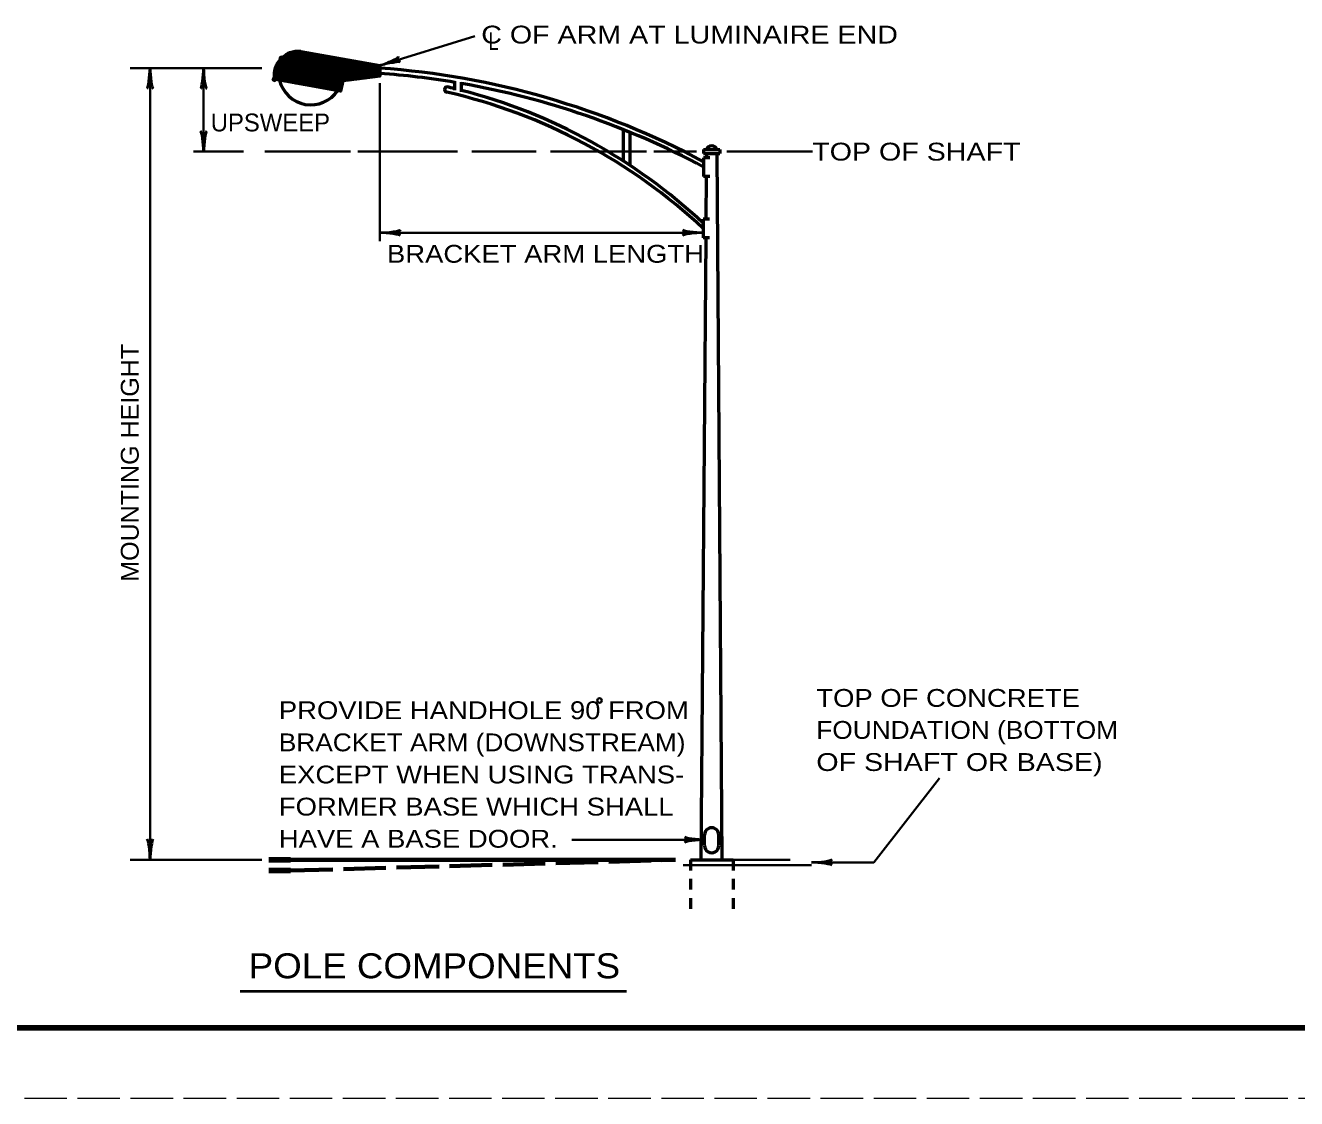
# Model space of a CAD drawing. Extents: x 6488 to 7168, y 276 to 716.
# Drawn here: x 6801.8 to 6981.4, y 276 to 427.7 of the extents above; entities that cross this region are included whole.
import ezdxf

# ---------------------------------------------------------------- set-up
doc = ezdxf.new("R2010")
doc.units = 0
doc.header["$PDMODE"] = 32
doc.header["$PDSIZE"] = 0.5
doc.linetypes.add('LONG_DASHED', pattern=[7.5, 6, -1.5])
doc.linetypes.add('SHORT_DASHED', pattern=[2.7, 1.5, -1.2])
doc.layers.add('1', color=7, linetype='Continuous', lineweight=35)
doc.layers.add('61', color=7, linetype='Continuous', lineweight=35)

msp = doc.modelspace()

# ---------------------------------------------------------------- linework, layer by layer
at = {"layer": '1'}
for p, q in [((6851.87, 421.998), (6865.29, 426.138)), ((6835.19, 421.618), (6816.59, 421.618)), ((6819.39, 421.618), (6819.39, 309.738)), ((6826.95, 409.818), (6826.95, 421.618)), ((6851.87, 419.478), (6851.87, 397.158)), ((6832.59, 409.818), (6825.55, 409.818)), ((6847.71, 409.818), (6835.63, 409.818)), ((6862.83, 409.818), (6848.73, 409.818)), ((6873.93, 409.818), (6864.85, 409.818)), ((6889.55, 409.818), (6875.95, 409.818)), ((6890.55, 409.818), (6896.61, 409.818)), ((6912.99, 409.818), (6900.89, 409.818)), ((6897.55, 398.358), (6851.87, 398.358)), ((6930.91, 321.278), (6921.65, 309.378)), ((6897.81, 312.578), (6878.97, 312.578)), ((6835.19, 309.738), (6816.59, 309.738)), ((6894.71, 308.978), (6912.85, 308.978)), ((6901.77, 309.738), (6909.83, 309.738)), ((6912.85, 309.378), (6921.65, 309.378))]:
    msp.add_line(p, q, dxfattribs=at)
at = {"layer": '1', "lineweight": 53}
for p, q in [((6836.99, 421.318), (6839.59, 423.898)), ((6837.03, 421.438), (6839.45, 423.858)), ((6837.51, 421.718), (6839.73, 423.918)), ((6837.63, 421.718), (6839.85, 423.958)), ((6837.73, 421.718), (6839.97, 423.958)), ((6837.83, 421.718), (6840.09, 423.978)), ((6837.95, 421.718), (6840.21, 423.978)), ((6838.05, 421.718), (6840.31, 423.978)), ((6838.15, 421.718), (6840.43, 423.978)), ((6838.27, 421.718), (6840.53, 423.978)), ((6838.37, 421.718), (6840.63, 423.978)), ((6838.47, 421.718), (6840.73, 423.978)), ((6838.59, 421.718), (6840.81, 423.958)), ((6838.69, 421.718), (6840.91, 423.938)), ((6838.79, 421.718), (6840.99, 423.918)), ((6838.91, 421.718), (6841.09, 423.898)), ((6839.01, 421.718), (6841.19, 423.898)), ((6839.11, 421.718), (6841.27, 423.878)), ((6839.23, 421.718), (6841.37, 423.858)), ((6837.09, 421.598), (6839.29, 423.818)), ((6837.13, 421.758), (6839.13, 423.758)), ((6837.21, 421.958), (6838.95, 423.678)), ((6837.31, 422.158), (6838.73, 423.578)), ((6837.47, 422.418), (6838.47, 423.418)), ((6839.33, 421.718), (6841.45, 423.838)), ((6839.43, 421.718), (6841.55, 423.818)), ((6839.55, 421.718), (6841.63, 423.818)), ((6839.65, 421.718), (6841.73, 423.798)), ((6839.77, 421.718), (6841.81, 423.778)), ((6839.87, 421.718), (6841.91, 423.758)), ((6839.97, 421.718), (6841.99, 423.738)), ((6840.09, 421.718), (6842.09, 423.738)), ((6840.19, 421.718), (6842.19, 423.718)), ((6840.29, 421.718), (6842.27, 423.698)), ((6840.41, 421.718), (6842.37, 423.678)), ((6840.51, 421.718), (6842.45, 423.658)), ((6840.61, 421.718), (6842.55, 423.658)), ((6840.73, 421.718), (6842.63, 423.638)), ((6840.83, 421.718), (6842.73, 423.618)), ((6840.93, 421.718), (6842.81, 423.598)), ((6841.05, 421.718), (6842.91, 423.578)), ((6841.15, 421.718), (6842.99, 423.558)), ((6841.25, 421.718), (6843.09, 423.558)), ((6841.37, 421.718), (6843.19, 423.538)), ((6841.47, 421.718), (6843.27, 423.518)), ((6841.57, 421.718), (6843.37, 423.498)), ((6841.69, 421.718), (6843.45, 423.478)), ((6841.79, 421.718), (6843.55, 423.478)), ((6841.89, 421.718), (6843.63, 423.458)), ((6842.01, 421.718), (6843.73, 423.438)), ((6842.11, 421.718), (6843.81, 423.418)), ((6842.21, 421.718), (6843.91, 423.398)), ((6842.33, 421.718), (6843.99, 423.398)), ((6842.43, 421.718), (6844.09, 423.378)), ((6842.55, 421.718), (6844.19, 423.358)), ((6842.65, 421.718), (6844.27, 423.338)), ((6842.75, 421.718), (6844.37, 423.318)), ((6842.87, 421.718), (6844.45, 423.318)), ((6842.97, 421.718), (6844.55, 423.298)), ((6843.07, 421.718), (6844.63, 423.278)), ((6843.19, 421.718), (6844.73, 423.258)), ((6843.29, 421.718), (6844.81, 423.238)), ((6843.39, 421.718), (6844.91, 423.238)), ((6843.51, 421.718), (6844.99, 423.218)), ((6843.61, 421.718), (6845.09, 423.198)), ((6843.71, 421.718), (6845.19, 423.178)), ((6843.83, 421.718), (6845.27, 423.158)), ((6843.93, 421.718), (6845.37, 423.158)), ((6844.03, 421.718), (6845.45, 423.138)), ((6844.15, 421.718), (6845.55, 423.118)), ((6844.25, 421.718), (6845.63, 423.098)), ((6844.35, 421.718), (6845.73, 423.078)), ((6844.47, 421.718), (6845.81, 423.078)), ((6844.57, 421.718), (6845.91, 423.058)), ((6844.67, 421.718), (6845.99, 423.038)), ((6844.79, 421.718), (6846.09, 423.018)), ((6844.89, 421.718), (6846.19, 422.998)), ((6844.99, 421.718), (6846.27, 422.998)), ((6845.11, 421.718), (6846.37, 422.978)), ((6845.21, 421.718), (6846.45, 422.958)), ((6845.31, 421.718), (6846.55, 422.938)), ((6845.43, 421.718), (6846.63, 422.918)), ((6845.53, 421.718), (6846.73, 422.918)), ((6845.65, 421.718), (6846.81, 422.898)), ((6845.75, 421.718), (6846.91, 422.878)), ((6845.85, 421.718), (6846.99, 422.858)), ((6845.97, 421.718), (6847.09, 422.838)), ((6846.07, 421.718), (6847.17, 422.838)), ((6846.17, 421.718), (6847.27, 422.818)), ((6846.29, 421.718), (6847.37, 422.798)), ((6846.39, 421.718), (6847.45, 422.778)), ((6846.49, 421.718), (6847.55, 422.758)), ((6846.61, 421.718), (6847.63, 422.758)), ((6846.71, 421.718), (6847.73, 422.738)), ((6846.81, 421.718), (6847.81, 422.718)), ((6846.93, 421.718), (6847.91, 422.698)), ((6847.03, 421.718), (6847.99, 422.678)), ((6847.13, 421.718), (6848.09, 422.678)), ((6847.25, 421.718), (6848.17, 422.658)), ((6847.35, 421.718), (6848.27, 422.638)), ((6847.45, 421.718), (6848.37, 422.618)), ((6847.57, 421.718), (6848.45, 422.598)), ((6847.67, 421.718), (6848.55, 422.598)), ((6847.77, 421.718), (6848.63, 422.578)), ((6847.89, 421.718), (6848.73, 422.558)), ((6847.99, 421.718), (6848.81, 422.538)), ((6848.09, 421.718), (6848.91, 422.518)), ((6848.21, 421.718), (6848.99, 422.518)), ((6848.31, 421.718), (6849.09, 422.498)), ((6848.43, 421.718), (6849.17, 422.478)), ((6848.53, 421.718), (6849.27, 422.458)), ((6848.63, 421.718), (6849.37, 422.438)), ((6848.75, 421.718), (6849.45, 422.438)), ((6848.85, 421.718), (6849.55, 422.418)), ((6848.95, 421.718), (6849.63, 422.398)), ((6849.07, 421.718), (6849.73, 422.378)), ((6849.17, 421.718), (6849.81, 422.358)), ((6849.27, 421.718), (6849.91, 422.358)), ((6849.39, 421.718), (6849.99, 422.338)), ((6849.49, 421.718), (6850.09, 422.318)), ((6849.59, 421.718), (6850.17, 422.298)), ((6849.71, 421.718), (6850.27, 422.278)), ((6849.81, 421.718), (6850.37, 422.278)), ((6849.91, 421.718), (6850.45, 422.258)), ((6850.03, 421.718), (6850.55, 422.238)), ((6850.13, 421.718), (6850.63, 422.218)), ((6850.23, 421.718), (6850.73, 422.198)), ((6850.35, 421.718), (6850.81, 422.198)), ((6850.45, 421.718), (6850.91, 422.178)), ((6850.55, 421.718), (6850.99, 422.158)), ((6850.67, 421.718), (6851.09, 422.138)), ((6850.77, 421.718), (6851.17, 422.118)), ((6850.87, 421.718), (6851.27, 422.118)), ((6850.99, 421.718), (6851.37, 422.098)), ((6851.09, 421.718), (6851.45, 422.078)), ((6851.21, 421.718), (6851.55, 422.058)), ((6836.91, 420.798), (6837.65, 421.538)), ((6836.91, 420.678), (6837.75, 421.538)), ((6836.91, 420.578), (6837.87, 421.538)), ((6836.91, 420.478), (6837.97, 421.538)), ((6836.91, 420.358), (6838.07, 421.538)), ((6836.91, 420.278), (6838.19, 421.538)), ((6836.93, 420.918), (6837.53, 421.538)), ((6836.93, 420.178), (6838.29, 421.538)), ((6836.93, 420.078), (6838.39, 421.538)), ((6836.95, 421.038), (6837.49, 421.598)), ((6836.97, 421.178), (6837.49, 421.698)), ((6836.99, 420.018), (6838.51, 421.538)), ((6837.09, 419.998), (6838.61, 421.538)), ((6837.17, 419.998), (6838.71, 421.538)), ((6837.27, 419.978), (6838.83, 421.538)), ((6837.35, 419.958), (6838.93, 421.538)), ((6837.45, 419.938), (6839.03, 421.538)), ((6837.53, 419.918), (6839.15, 421.538)), ((6837.63, 419.918), (6839.25, 421.538)), ((6837.73, 419.898), (6839.35, 421.538)), ((6837.81, 419.878), (6839.47, 421.538)), ((6837.91, 419.858), (6839.57, 421.538)), ((6837.99, 419.838), (6839.67, 421.538)), ((6838.09, 419.838), (6839.79, 421.538)), ((6838.17, 419.818), (6839.89, 421.538)), ((6838.27, 419.798), (6839.99, 421.538)), ((6838.35, 419.778), (6840.11, 421.538)), ((6838.45, 419.758), (6840.21, 421.538)), ((6838.53, 419.758), (6840.31, 421.538)), ((6838.63, 419.738), (6840.43, 421.538)), ((6838.71, 419.718), (6840.53, 421.538)), ((6838.81, 419.698), (6840.65, 421.538)), ((6838.91, 419.678), (6840.75, 421.538)), ((6838.99, 419.678), (6840.85, 421.538)), ((6839.09, 419.658), (6840.97, 421.538)), ((6839.17, 419.638), (6841.07, 421.538)), ((6839.27, 419.618), (6841.17, 421.538)), ((6839.35, 419.598), (6841.29, 421.538)), ((6839.45, 419.598), (6841.39, 421.538)), ((6839.53, 419.578), (6841.49, 421.538)), ((6839.63, 419.558), (6841.61, 421.538)), ((6839.71, 419.538), (6841.71, 421.538)), ((6839.81, 419.518), (6841.81, 421.538)), ((6839.91, 419.518), (6841.93, 421.538)), ((6839.99, 419.498), (6842.03, 421.538)), ((6840.09, 419.478), (6842.13, 421.538)), ((6840.17, 419.458), (6842.25, 421.538)), ((6840.27, 419.438), (6842.35, 421.538)), ((6840.35, 419.438), (6842.45, 421.538)), ((6840.45, 419.418), (6842.57, 421.538)), ((6840.53, 419.398), (6842.67, 421.538)), ((6840.63, 419.378), (6842.77, 421.538)), ((6840.71, 419.358), (6842.89, 421.538)), ((6840.81, 419.338), (6842.99, 421.538)), ((6840.91, 419.338), (6843.09, 421.538)), ((6840.99, 419.318), (6843.21, 421.538)), ((6841.09, 419.298), (6843.31, 421.538)), ((6841.17, 419.278), (6843.43, 421.538)), ((6841.27, 419.258), (6843.53, 421.538)), ((6841.35, 419.258), (6843.63, 421.538)), ((6841.45, 419.238), (6843.75, 421.538)), ((6841.53, 419.218), (6843.85, 421.538)), ((6841.63, 419.198), (6843.95, 421.538)), ((6841.71, 419.178), (6844.07, 421.538)), ((6841.81, 419.178), (6844.17, 421.538)), ((6841.91, 419.158), (6844.27, 421.538)), ((6841.99, 419.138), (6844.39, 421.538)), ((6842.09, 419.118), (6844.49, 421.538)), ((6842.17, 419.098), (6844.59, 421.538)), ((6842.27, 419.098), (6844.71, 421.538)), ((6842.35, 419.078), (6844.81, 421.538)), ((6842.45, 419.058), (6844.91, 421.538)), ((6842.53, 419.038), (6845.03, 421.538)), ((6842.63, 419.018), (6845.13, 421.538)), ((6842.71, 419.018), (6845.23, 421.538)), ((6842.81, 418.998), (6845.35, 421.538)), ((6842.91, 418.978), (6845.45, 421.538)), ((6842.99, 418.958), (6845.55, 421.538)), ((6843.09, 418.938), (6845.67, 421.538)), ((6843.17, 418.938), (6845.77, 421.538)), ((6843.27, 418.918), (6845.87, 421.538)), ((6843.35, 418.898), (6845.99, 421.538)), ((6843.45, 418.878), (6846.09, 421.538)), ((6843.53, 418.858), (6846.21, 421.538)), ((6843.63, 418.858), (6846.31, 421.538)), ((6843.71, 418.838), (6846.41, 421.538)), ((6843.81, 418.818), (6846.53, 421.538)), ((6843.91, 418.798), (6846.63, 421.538)), ((6843.99, 418.778), (6846.73, 421.538)), ((6844.09, 418.778), (6846.85, 421.538)), ((6844.17, 418.758), (6846.95, 421.538)), ((6844.27, 418.738), (6847.05, 421.538)), ((6844.35, 418.718), (6847.17, 421.538)), ((6844.45, 418.698), (6847.27, 421.538)), ((6844.53, 418.698), (6847.37, 421.538)), ((6844.63, 418.678), (6847.49, 421.538)), ((6844.71, 418.658), (6847.59, 421.538)), ((6844.81, 418.638), (6847.69, 421.538)), ((6844.91, 418.618), (6847.81, 421.538)), ((6844.99, 418.618), (6847.91, 421.538)), ((6845.09, 418.598), (6848.01, 421.538)), ((6845.17, 418.578), (6848.13, 421.538)), ((6845.27, 418.558), (6848.23, 421.538)), ((6846.65, 419.858), (6848.33, 421.538)), ((6846.79, 419.858), (6848.45, 421.538)), ((6846.91, 419.878), (6848.55, 421.538)), ((6847.03, 419.898), (6848.65, 421.538)), ((6847.15, 419.918), (6848.77, 421.538)), ((6847.27, 419.918), (6848.87, 421.538)), ((6847.39, 419.938), (6848.97, 421.538)), ((6847.51, 419.958), (6849.09, 421.538)), ((6847.63, 419.978), (6849.19, 421.538)), ((6847.75, 419.978), (6849.31, 421.538)), ((6847.87, 419.998), (6849.41, 421.538)), ((6847.99, 420.018), (6849.51, 421.538)), ((6848.13, 420.038), (6849.63, 421.538)), ((6848.25, 420.038), (6849.73, 421.538)), ((6848.37, 420.058), (6849.83, 421.538)), ((6848.49, 420.078), (6849.95, 421.538)), ((6848.61, 420.098), (6850.05, 421.538)), ((6848.73, 420.098), (6850.15, 421.538)), ((6848.85, 420.118), (6850.27, 421.538)), ((6848.97, 420.138), (6850.37, 421.538)), ((6849.09, 420.158), (6850.47, 421.538)), ((6849.21, 420.158), (6850.59, 421.538)), ((6849.33, 420.178), (6850.69, 421.538)), ((6849.47, 420.198), (6850.79, 421.538)), ((6849.59, 420.218), (6850.91, 421.538)), ((6849.71, 420.218), (6851.01, 421.538)), ((6849.83, 420.238), (6851.11, 421.538)), ((6849.95, 420.258), (6851.23, 421.538)), ((6850.07, 420.278), (6851.33, 421.538)), ((6850.19, 420.278), (6851.43, 421.538)), ((6850.31, 420.298), (6851.87, 421.858)), ((6850.43, 420.318), (6851.87, 421.758)), ((6850.55, 420.338), (6851.87, 421.638)), ((6850.69, 420.338), (6851.87, 421.538)), ((6850.81, 420.358), (6851.87, 421.438)), ((6850.93, 420.378), (6851.87, 421.318)), ((6851.05, 420.398), (6851.87, 421.218)), ((6851.17, 420.398), (6851.87, 421.118)), ((6851.29, 420.418), (6851.87, 420.998)), ((6851.31, 421.718), (6851.63, 422.038)), ((6851.41, 421.718), (6851.73, 422.038)), ((6851.41, 420.438), (6851.87, 420.898)), ((6851.49, 421.698), (6851.81, 422.018)), ((6851.49, 421.598), (6851.87, 421.958)), ((6851.53, 420.458), (6851.87, 420.798)), ((6851.65, 420.458), (6851.87, 420.678)), ((6851.77, 420.478), (6851.87, 420.578)), ((6845.35, 418.538), (6846.61, 419.798)), ((6845.45, 418.538), (6846.59, 419.658)), ((6845.53, 418.518), (6846.55, 419.518)), ((6845.63, 418.498), (6846.51, 419.398)), ((6845.71, 418.478), (6846.49, 419.258)), ((6845.81, 418.458), (6846.45, 419.118)), ((6845.89, 418.458), (6846.43, 418.978)), ((6845.99, 418.438), (6846.39, 418.838)), ((6846.09, 418.418), (6846.35, 418.698)), ((6846.17, 418.398), (6846.33, 418.558)), ((6862.45, 418.518), (6862.45, 419.798)), ((6863.41, 418.278), (6863.41, 419.638)), ((6846.27, 418.378), (6846.29, 418.418)), ((6886.27, 408.478), (6886.27, 412.938)), ((6887.21, 407.878), (6887.21, 412.538)), ((6897.61, 410.098), (6899.89, 410.098)), ((6897.61, 410.098), (6897.61, 409.538)), ((6897.61, 409.538), (6899.89, 409.538)), ((6897.99, 409.538), (6897.99, 408.958)), ((6900.25, 309.738), (6899.51, 409.538)), ((6899.89, 410.098), (6899.89, 409.538)), ((6898.49, 408.958), (6897.61, 408.958)), ((6897.61, 408.958), (6897.61, 406.318)), ((6898.49, 406.318), (6897.61, 406.318)), ((6897.97, 406.318), (6897.93, 400.258)), ((6898.43, 400.258), (6897.55, 400.258)), ((6897.55, 400.258), (6897.55, 397.618)), ((6897.91, 397.618), (6897.23, 309.738)), ((6898.43, 397.618), (6897.55, 397.618)), ((6897.75, 311.758), (6897.75, 313.258)), ((6899.75, 311.758), (6899.75, 313.258)), ((6895.73, 309.738), (6901.77, 309.738))]:
    msp.add_line(p, q, dxfattribs=at)
at = {"layer": '1', "lineweight": 106}
for p, q in [((6836.19, 309.738), (6839.23, 309.738)), ((6836.19, 308.218), (6839.23, 308.218))]:
    msp.add_line(p, q, dxfattribs=at)
at = {"layer": '1', "lineweight": 70}
msp.add_line((6839.23, 309.738), (6893.65, 309.738), dxfattribs=at)
at = {"layer": '1', "linetype": 'LONG_DASHED', "lineweight": 70}
msp.add_line((6839.23, 308.218), (6893.65, 309.738), dxfattribs=at)
at = {"layer": '1', "linetype": 'SHORT_DASHED', "lineweight": 53}
for p, q in [((6895.73, 309.738), (6895.73, 301.678)), ((6901.77, 309.738), (6901.77, 301.678))]:
    msp.add_line(p, q, dxfattribs=at)
at = {"layer": '1', "lineweight": 40}
msp.add_line((6832.11, 291.178), (6886.69, 291.178), dxfattribs=at)
at = {"layer": '1', "lineweight": 53}
msp.add_lwpolyline([(6840.71, 423.978), (6851.87, 421.998), (6851.87, 420.498), (6846.63, 419.838), (6846.29, 418.378), (6836.95, 420.038)], dxfattribs=at)
msp.add_lwpolyline([(6837.49, 421.718), (6851.49, 421.718), (6851.49, 421.538), (6837.49, 421.538)], close=True, dxfattribs=at)
at = {"layer": '1'}
msp.add_circle((6882.902, 332.255), 0.325, dxfattribs=at)
at = {"layer": '1', "lineweight": 53}
for centre, radius, start, end in [((6840.361, 420.534), 3.456, 84.23953, 188.38162), ((6843.679, 307.63), 114.289, 61.84402, 85.88743), ((6843.679, 306.874), 114.289, 80.54208, 85.88743), ((6842.122, 421.001), 4.57, 193.94762, 326.05059), ((6861.388, 418.601), 0.383, 99.37484, 260.62516), ((6843.798, 342.391), 78.568, 76.2603, 77.11012), ((6843.679, 306.874), 114.289, 61.84402, 80.06146), ((6843.798, 342.391), 78.568, 46.83897, 75.54976), ((6861.5, 418.85), 0.651, 235.53017, 254.38288), ((6843.798, 341.635), 78.568, 46.83897, 77.11012), ((6898.747, 409.817), 0.802, 20.3922, 159.6078), ((6898.747, 313.286), 0.993, 358.58875, 181.41125), ((6898.747, 311.713), 0.993, 178.58875, 1.41125)]:
    msp.add_arc(centre, radius, start, end, dxfattribs=at)
at = {"layer": '1', "lineweight": 40}
for centre, major_axis, ratio, start_param, end_param in [((6852.844, 422.593), (-1.674, -0.68), 0.122415, 0.8963533, 3.1415927), ((6853.017, 422.132), (1.744, 0.352), 0.07063, 6.2823074, 8.5597026), ((6819.185, 420.496), (0.177, 1.77), 0.07063, 3.1407148, 5.41811), ((6819.677, 420.525), (-0.157, 1.8), 0.122415, 0.8963533, 3.1415927), ((6826.746, 420.496), (0.177, 1.77), 0.07063, 3.1407148, 5.41811), ((6827.237, 420.525), (-0.157, 1.8), 0.122415, 0.8963533, 3.1415927), ((6826.68, 410.913), (0.157, -1.8), 0.122415, 0.8963533, 3.1415927), ((6827.172, 410.942), (-0.177, -1.77), 0.07063, 3.1407148, 5.41811), ((6852.975, 398.641), (-1.8, -0.157), 0.122415, 0.8963533, 3.1415927), ((6852.975, 398.641), (-1.8, -0.157), 0.122415, 0.8963533, 3.1415927), ((6896.414, 398.576), (1.77, -0.177), 0.07063, 3.1407148, 5.41811), ((6896.414, 398.576), (1.77, -0.177), 0.07063, 3.1407148, 5.41811), ((6853.005, 398.149), (-1.77, 0.177), 0.07063, 3.1407148, 5.41811), ((6853.005, 398.149), (-1.77, 0.177), 0.07063, 3.1407148, 5.41811), ((6896.443, 398.084), (1.8, 0.157), 0.122415, 0.8963533, 3.1415927), ((6896.443, 398.084), (1.8, 0.157), 0.122415, 0.8963533, 3.1415927), ((6819.12, 310.837), (0.157, -1.8), 0.122415, 0.8963533, 3.1415927), ((6819.612, 310.867), (-0.177, -1.77), 0.07063, 3.1407148, 5.41811), ((6896.717, 312.303), (1.8, 0.157), 0.122415, 0.8963533, 3.1415927), ((6896.688, 312.795), (1.77, -0.177), 0.07063, 3.1407148, 5.41811), ((6913.955, 309.653), (-1.8, -0.157), 0.122415, 0.8963533, 3.1415927), ((6913.985, 309.161), (-1.77, 0.177), 0.07063, 3.1407148, 5.41811)]:
    msp.add_ellipse(centre, major_axis=major_axis, ratio=ratio, start_param=start_param, end_param=end_param, dxfattribs=at)
at = {"layer": '1'}
for p in [(6837.95, 422.998), (6836.95, 420.038)]:
    msp.add_point(p, dxfattribs=at)
at = {"layer": '61', "lineweight": 158}
msp.add_line((7156.703, 286), (6517.643, 286.02), dxfattribs=at)
at = {"layer": '61', "linetype": 'LONG_DASHED', "lineweight": 13}
msp.add_line((7167.643, 276.02), (6487.583, 276), dxfattribs=at)

# ---------------------------------------------------------------- texts
at = {"layer": '1'}
for s, height, width, p in [('C OF ARM AT LUMINAIRE END', 2.52, 1.2, (6866.19, 425.098)), ('L', 2.52, 0.75, (6867.21, 424.178)), ('TOP OF SHAFT', 2.52, 1.2, (6912.95, 408.558)), ('BRACKET ARM LENGTH', 2.52, 1.15, (6852.87, 394.118)), ('TOP OF CONCRETE', 2.52, 1.15, (6913.53, 331.358)), ('PROVIDE HANDHOLE 90 FROM', 2.52, 1.15, (6837.59, 329.618)), ('FOUNDATION (BOTTOM', 2.52, 1.1, (6913.53, 326.838)), ('BRACKET ARM (DOWNSTREAM)', 2.52, 1.1, (6837.59, 325.078)), ('OF SHAFT OR BASE)', 2.52, 1.2, (6913.53, 322.298)), ('EXCEPT WHEN USING TRANS-', 2.52, 1.15, (6837.59, 320.538)), ('FORMER BASE WHICH SHALL', 2.52, 1.15, (6837.59, 315.998)), ('HAVE A BASE DOOR.', 2.52, 1.15, (6837.59, 311.458)), ('POLE COMPONENTS', 3.528, 1.1, (6833.33, 292.998))]:
    msp.add_text(s, height=height, dxfattribs=dict(at, width=width)).set_placement(p)
msp.add_text('UPSWEEP', height=2.52, dxfattribs=at).set_placement((6827.97, 412.678))
at = {"layer": '1', "width": 1.05}
msp.add_text('MOUNTING HEIGHT', height=2.52, rotation=90, dxfattribs=at).set_placement((6817.79, 349.038))

doc.saveas('drawing.dxf')
